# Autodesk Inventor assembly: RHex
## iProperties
Author: Standard
Created: 2002-11
Part Number: RHex
Document SubType Name: Baugruppe
Designer: Standard
Control State: 0
Master: False
Checked Out: False
PropertySet Name: Design Tracking Control
Shininess: 20.0
Angle Display Precision: 2
Document Length Units: 11269
Document Angle Units: 11283
Document Time Units: 11279
Document Mass Units: 11290
Document Length Units Precision: 3
Document Angle Units Precision: 2
Compacted: False
PropertySet Name: _Private Model Information
Density: 0.0
Volumn: 0.0
Area: 0.0
PropertySet Name: Model Information
